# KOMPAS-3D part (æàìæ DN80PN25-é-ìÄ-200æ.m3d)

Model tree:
1. Объединить компоненты:1  (labels: СЕНС DN80PN25-В-НО-200С)

Referenced files in D:\Савин\!СЕНСОР\3D для заказчика\!Новый перечень\СЕНС\7. СЕНС-В-НО-200С\DN80\: СЕНС DN80PN25-В-НО-200С.a3d
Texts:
  СЕНС DN80PN25-В-НО-200С
  ООО НПП Сенсор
